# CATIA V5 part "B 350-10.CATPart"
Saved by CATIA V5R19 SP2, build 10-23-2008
Part number: B 350-10
Bounding box of the stored display mesh (mm): x -15.868 to 15.868, y -15.868 to 15.868, z 0 to 70
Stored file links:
  C:\Users\Bora\Desktop\3D Katı model\B serisi\B 350\B 350-10.CATPart
  C:\Program Files\Dassault Systemes\B19\intel_a\reffiles\standard\MetricThickPitch.txt
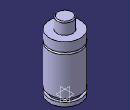
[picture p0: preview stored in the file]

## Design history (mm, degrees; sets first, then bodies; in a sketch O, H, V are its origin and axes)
Body1 (main body)
  Sketch1 on yz-plane, origin (0, 0, 0), H (0, 1, 0), V (0, 0, 1)
    point P1 (16, 48.5)
    point P4 (16, 46.5)
    point P7 (16, 48.5)
    point P8 (16, 46.5)
    point P9 (8, 69)
    point P11 (8, 69)
    line L1 (16, 48.5) -> (16, 58)
    line L2 (16, 7.5) -> (16, 46.5)
    line L3 (13.5, 7.5) -> (13.5, 4)
    arc A1 centre (16, 47.5) radius 1 from (16, 48.5) to (16, 46.5) ccw
    arc A2 centre (7, 69) radius 1 from (8, 69) to (7, 70) ccw
    line L4 (8, 69) -> (8, 58)
    line L5 (16, 0) -> (16, 4)
    line L6 (7, 70) -> (0, 70)
    point P15 (0, 70)
    line L7 (8, 58) -> (16, 58)
    line L8 (0, 0) -> (16, 0)
    line L9 (13.5, 7.5) -> (16, 7.5)
    line L10 (13.5, 4) -> (16, 4)
    coincidence: P15 V, P1 P7, P4 P8, P9 P11
    tangency: L6 A2
    horizontal: L7 H, L8 H, L9 H, L10 H
  Shaft1: profile Sketch1, axis Sketch1.V, angle 360
  Sketch2 on face of Shaft1 from Sketch1.L8, origin (0, 0, 0), H (1, 0, 0), V (0, -1, 0)
    point P1 (0, 0)
  Hole1: placed by Sketch2, at (0, 0, 0) direction (0, 0, 1), diameter 6.647, depth 7, threaded "M8", thread diameter 8, thread depth 7, pitch 1.25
